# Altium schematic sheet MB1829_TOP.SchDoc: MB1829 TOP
size A4; Date: Not used; ApprovedBy: Not used; CheckedBy: Not used; Author: Not used; CompanyName: STMicroelectronics; DrawnBy: Not used; Engineer: Not used; Organization: Not used; Address1: Not used; Address2: Not used; Address3: Not used; Address4: Not used; DocumentNumber: Not used; Revision: Not used; SheetNumber: 2; SheetTotal: 16
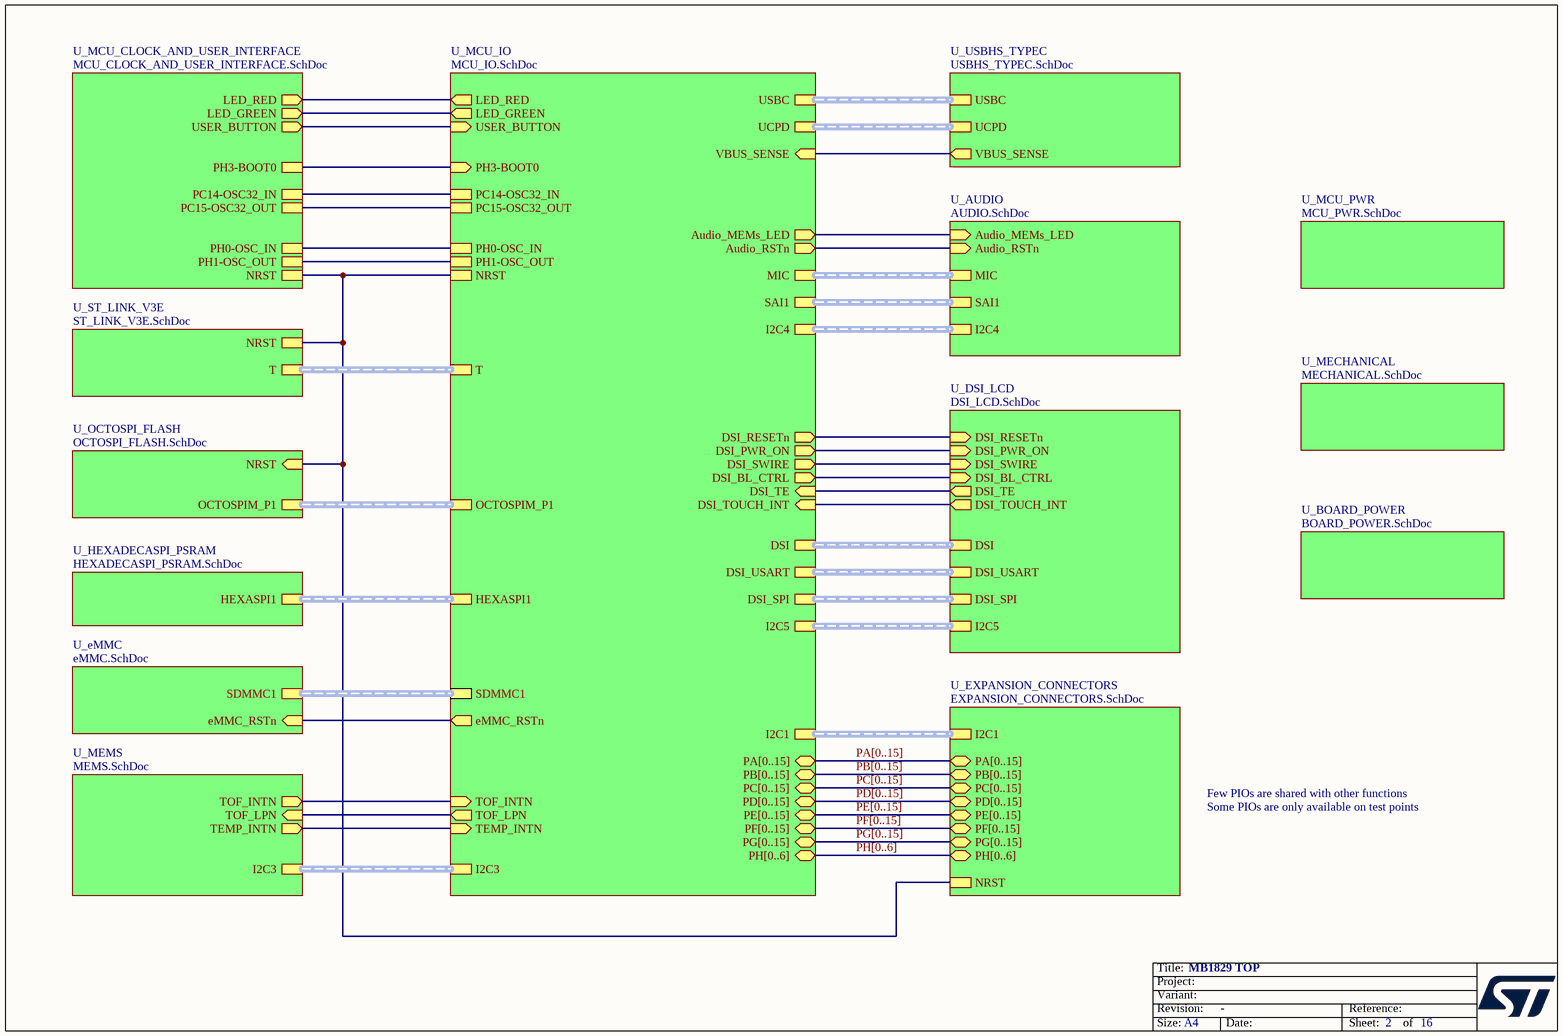
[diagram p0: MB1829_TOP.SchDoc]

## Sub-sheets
U_AUDIO = AUDIO.SchDoc: MIC (harness MIC), I2C4 (harness I2C4), SAI1 (harness SAI), Audio_RSTn (in), Audio_MEMs_LED (in)
U_BOARD_POWER = BOARD_POWER.SchDoc: no entries
U_DSI_LCD = DSI_LCD.SchDoc: DSI_RESETn (in), DSI_PWR_ON (in), DSI_SWIRE (in), DSI_BL_CTRL (in), DSI_TE (out), DSI_TOUCH_INT (out), DSI (harness DSI_LANES), I2C5 (harness I2C5), DSI_USART (harness DSI_USART), DSI_SPI (harness DSI_SPI)
U_eMMC = eMMC.SchDoc: eMMC_RSTn (in), SDMMC1 (harness eMMC)
U_EXPANSION_CONNECTORS = EXPANSION_CONNECTORS.SchDoc: NRST, I2C1 (harness I2C1), PC[0..15] (bidir), PA[0..15] (bidir), PB[0..15] (bidir), PD[0..15] (bidir), PE[0..15] (bidir), PH[0..6] (bidir), PF[0..15] (bidir), PG[0..15] (bidir)
U_HEXADECASPI_PSRAM = HEXADECASPI_PSRAM.SchDoc: HEXASPI1 (harness HEXASPI1)
U_MCU_CLOCK_AND_USER_INTERFACE = MCU_CLOCK_AND_USER_INTERFACE.SchDoc: NRST, PH3-BOOT0, PC14-OSC32_IN, PC15-OSC32_OUT, LED_RED (out), LED_GREEN (out), PH0-OSC_IN, PH1-OSC_OUT, USER_BUTTON (out)
U_MCU_IO = MCU_IO.SchDoc: PH3-BOOT0 (in), NRST, PH0-OSC_IN, PH1-OSC_OUT, PC14-OSC32_IN, PC15-OSC32_OUT, LED_RED (out), LED_GREEN (out), OCTOSPIM_P1 (harness OCTOSPI1), USBC (harness USBC), MIC (harness MIC), T (harness T), HEXASPI1 (harness HEXASPI1), SDMMC1 (harness eMMC), eMMC_RSTn (out), I2C4 (harness I2C4), SAI1 (harness SAI), USER_BUTTON (in), Audio_RSTn (out), I2C5 (harness I2C5), DSI_RESETn (out), DSI_PWR_ON (out), DSI_SWIRE (out), DSI_BL_CTRL (out), DSI_TE (in), DSI_TOUCH_INT (in), DSI_SPI (harness DSI_SPI), DSI_USART (harness DSI_USART), DSI (harness DSI_LANES), UCPD (harness UCPD_CTRL), VBUS_SENSE (in), PA[0..15] (bidir), PC[0..15] (bidir), PB[0..15] (bidir), PD[0..15] (bidir), PE[0..15] (bidir), PH[0..6] (bidir), PF[0..15] (bidir), PG[0..15] (bidir), I2C1 (harness I2C1), I2C3 (harness I2C3), TOF_INTN (in), TEMP_INTN (in), TOF_LPN (out), Audio_MEMs_LED (out)
U_MCU_PWR = MCU_PWR.SchDoc: no entries
U_MECHANICAL = MECHANICAL.SchDoc: no entries
U_MEMS = MEMS.SchDoc: I2C3 (harness I2C3), TOF_INTN (out), TOF_LPN (in), TEMP_INTN (out)
U_OCTOSPI_FLASH = OCTOSPI_FLASH.SchDoc: NRST (in), OCTOSPIM_P1 (harness OCTOSPI1)
U_ST_LINK_V3E = ST_LINK_V3E.SchDoc: NRST, T (harness T)
U_USBHS_TYPEC = USBHS_TYPEC.SchDoc: USBC (harness USBC), UCPD (harness UCPD_CTRL), VBUS_SENSE (out)

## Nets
(unnamed): sheet U_EXPANSION_CONNECTORS/NRST, sheet U_MCU_CLOCK_AND_USER_INTERFACE/NRST, sheet U_MCU_IO/NRST, sheet U_OCTOSPI_FLASH/NRST, sheet U_ST_LINK_V3E/NRST
(unnamed): sheet U_AUDIO/Audio_RSTn, sheet U_MCU_IO/Audio_RSTn  [a separate net that carries the same name]
(unnamed): sheet U_AUDIO/Audio_MEMs_LED, sheet U_MCU_IO/Audio_MEMs_LED  [a separate net that carries the same name]
(unnamed): sheet U_MCU_CLOCK_AND_USER_INTERFACE/PH3-BOOT0, sheet U_MCU_IO/PH3-BOOT0  [a separate net that carries the same name]
(unnamed): sheet U_MCU_CLOCK_AND_USER_INTERFACE/PC14-OSC32_IN, sheet U_MCU_IO/PC14-OSC32_IN  [a separate net that carries the same name]
(unnamed): sheet U_MCU_CLOCK_AND_USER_INTERFACE/PC15-OSC32_OUT, sheet U_MCU_IO/PC15-OSC32_OUT  [a separate net that carries the same name]
(unnamed): sheet U_MCU_CLOCK_AND_USER_INTERFACE/LED_RED, sheet U_MCU_IO/LED_RED  [a separate net that carries the same name]
(unnamed): sheet U_MCU_CLOCK_AND_USER_INTERFACE/LED_GREEN, sheet U_MCU_IO/LED_GREEN  [a separate net that carries the same name]
(unnamed): sheet U_MCU_CLOCK_AND_USER_INTERFACE/PH0-OSC_IN, sheet U_MCU_IO/PH0-OSC_IN  [a separate net that carries the same name]
(unnamed): sheet U_MCU_CLOCK_AND_USER_INTERFACE/PH1-OSC_OUT, sheet U_MCU_IO/PH1-OSC_OUT  [a separate net that carries the same name]
(unnamed): sheet U_MCU_CLOCK_AND_USER_INTERFACE/USER_BUTTON, sheet U_MCU_IO/USER_BUTTON  [a separate net that carries the same name]
(unnamed): sheet U_MCU_IO/eMMC_RSTn, sheet U_eMMC/eMMC_RSTn  [a separate net that carries the same name]
(unnamed): sheet U_MCU_IO/DSI_RESETn, sheet U_DSI_LCD/DSI_RESETn  [a separate net that carries the same name]
(unnamed): sheet U_MCU_IO/DSI_PWR_ON, sheet U_DSI_LCD/DSI_PWR_ON  [a separate net that carries the same name]
(unnamed): sheet U_MCU_IO/DSI_SWIRE, sheet U_DSI_LCD/DSI_SWIRE  [a separate net that carries the same name]
(unnamed): sheet U_MCU_IO/DSI_BL_CTRL, sheet U_DSI_LCD/DSI_BL_CTRL  [a separate net that carries the same name]
(unnamed): sheet U_MCU_IO/DSI_TE, sheet U_DSI_LCD/DSI_TE  [a separate net that carries the same name]
(unnamed): sheet U_MCU_IO/DSI_TOUCH_INT, sheet U_DSI_LCD/DSI_TOUCH_INT  [a separate net that carries the same name]
(unnamed): sheet U_MCU_IO/VBUS_SENSE, sheet U_USBHS_TYPEC/VBUS_SENSE  [a separate net that carries the same name]
(unnamed): sheet U_MCU_IO/TOF_INTN, sheet U_MEMS/TOF_INTN  [a separate net that carries the same name]
(unnamed): sheet U_MCU_IO/TEMP_INTN, sheet U_MEMS/TEMP_INTN  [a separate net that carries the same name]
(unnamed): sheet U_MCU_IO/TOF_LPN, sheet U_MEMS/TOF_LPN  [a separate net that carries the same name]

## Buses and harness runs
bus PA[0..15] = sheet U_EXPANSION_CONNECTORS/PA[0..15] = sheet U_MCU_IO/PA[0..15]
bus PB[0..15] = sheet U_EXPANSION_CONNECTORS/PB[0..15] = sheet U_MCU_IO/PB[0..15]
bus PC[0..15] = sheet U_EXPANSION_CONNECTORS/PC[0..15] = sheet U_MCU_IO/PC[0..15]
bus PD[0..15] = sheet U_EXPANSION_CONNECTORS/PD[0..15] = sheet U_MCU_IO/PD[0..15]
bus PE[0..15] = sheet U_EXPANSION_CONNECTORS/PE[0..15] = sheet U_MCU_IO/PE[0..15]
bus PF[0..15] = sheet U_EXPANSION_CONNECTORS/PF[0..15] = sheet U_MCU_IO/PF[0..15]
bus PG[0..15] = sheet U_EXPANSION_CONNECTORS/PG[0..15] = sheet U_MCU_IO/PG[0..15]
bus PH[0..6] = sheet U_EXPANSION_CONNECTORS/PH[0..6] = sheet U_MCU_IO/PH[0..6]
harness sheet U_AUDIO/I2C4 = sheet U_MCU_IO/I2C4
harness sheet U_AUDIO/MIC = sheet U_MCU_IO/MIC
harness sheet U_AUDIO/SAI1 = sheet U_MCU_IO/SAI1
harness sheet U_DSI_LCD/DSI = sheet U_MCU_IO/DSI
harness sheet U_DSI_LCD/DSI_SPI = sheet U_MCU_IO/DSI_SPI
harness sheet U_DSI_LCD/DSI_USART = sheet U_MCU_IO/DSI_USART
harness sheet U_DSI_LCD/I2C5 = sheet U_MCU_IO/I2C5
harness sheet U_eMMC/SDMMC1 = sheet U_MCU_IO/SDMMC1
harness sheet U_EXPANSION_CONNECTORS/I2C1 = sheet U_MCU_IO/I2C1
harness sheet U_HEXADECASPI_PSRAM/HEXASPI1 = sheet U_MCU_IO/HEXASPI1
harness sheet U_MCU_IO/I2C3 = sheet U_MEMS/I2C3
harness sheet U_MCU_IO/OCTOSPIM_P1 = sheet U_OCTOSPI_FLASH/OCTOSPIM_P1
harness sheet U_MCU_IO/T = sheet U_ST_LINK_V3E/T
harness sheet U_MCU_IO/UCPD = sheet U_USBHS_TYPEC/UCPD
harness sheet U_MCU_IO/USBC = sheet U_USBHS_TYPEC/USBC

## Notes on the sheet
- Few PIOs are shared with other functions
- Some PIOs are only available on test points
